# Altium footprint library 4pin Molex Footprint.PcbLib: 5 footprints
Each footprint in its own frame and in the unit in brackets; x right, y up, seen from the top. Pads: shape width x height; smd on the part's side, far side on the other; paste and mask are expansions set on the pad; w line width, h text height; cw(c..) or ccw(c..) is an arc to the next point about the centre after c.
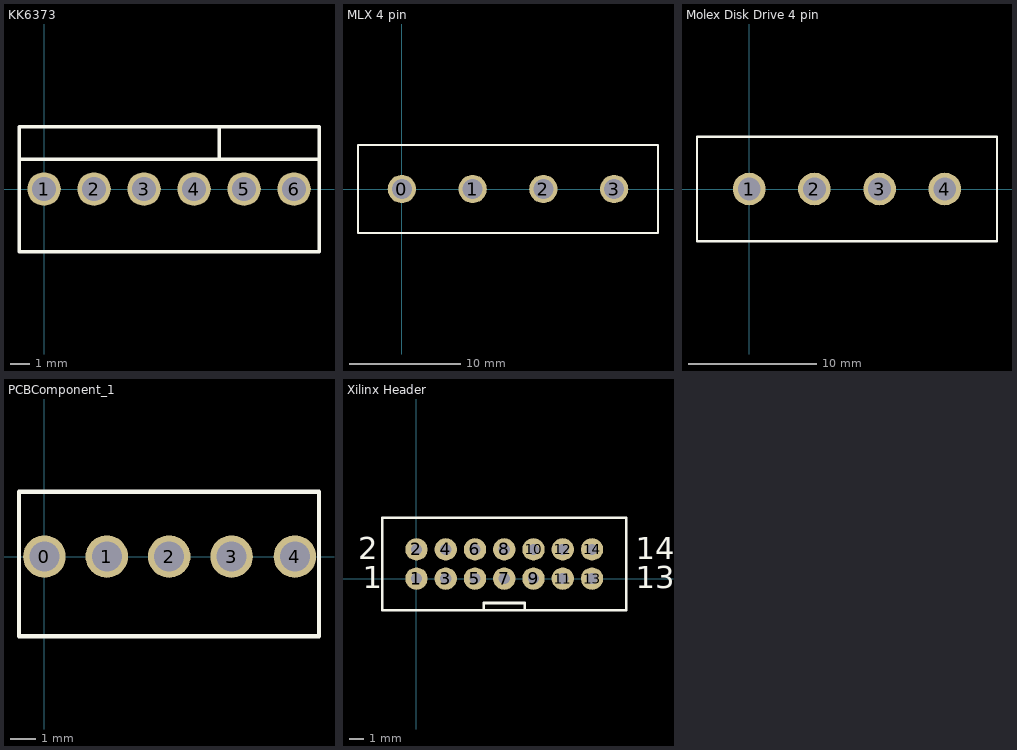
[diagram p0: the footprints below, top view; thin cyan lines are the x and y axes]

## KK6373 [mil]
pads (6):
  round 67 hole 47.24: 1(0,0) 2(100,0) 3(200,0) 4(300,0) 5(400,0) 6(500,0)
Top Overlay:
  lines w7: -50,60 350,60 ; 350,125 350,60 ; 550,60 350,60 ; -50,-125 550,-125 550,125 -50,125 -50,-125

## MLX 4 pin [mil]
pads (4):
  round 100 hole 70: 0(0,0) 1(250,0) 2(500,0) 3(750,0)
Top Overlay:
  lines w7: -155,-155 -155,155 905,155 905,-155 -155,-155

## Molex Disk Drive 4 pin [mil]
pads (4):
  round 100 hole 70: 1(0,0) 2(200,0) 3(400,0) 4(600,0)
Top Overlay:
  lines w7: -160,-160 760,-160 760,160 -160,160 -160,-160

## PCBComponent_1 [mil]
pads (5):
  round 67 hole 47.24: 0(0,0) 1(98.43,0) 2(196.85,0) 3(295.28,0) 4(395,0)
Top Overlay:
  lines w7: -40,-125.98 -40,-100 -40,102.36 433.07,102.36 433.07,-100 433.07,-125.98 -40,-125.98

## Xilinx Header [mil]
pads (14):
  round 60 hole 30: 1(0,0) 2(0,78.74) 3(78.74,0) 4(78.74,78.74) 5(157.48,0) 6(157.48,78.74) 7(236.22,0) 8(236.22,78.74) 9(314.96,0) 10(314.96,78.74) 11(393.7,0) 12(393.7,78.74) 13(472.44,0) 14(472.44,78.74)
Top Overlay:
  lines w7: 181.1,-84.41 181.1,-65.55 291.34,-65.55 291.34,-81.73 ; -91.73,-84.65 -91.73,163.39 564.17,163.39 564.17,-84.65 -91.73,-84.65
  text "14" at 589.96,52.44 h60
  text "13" at 589.96,-26.22 h60
  text "2" at -157.32,52.44 h60
  text "1" at -144.21,-26.22 h60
